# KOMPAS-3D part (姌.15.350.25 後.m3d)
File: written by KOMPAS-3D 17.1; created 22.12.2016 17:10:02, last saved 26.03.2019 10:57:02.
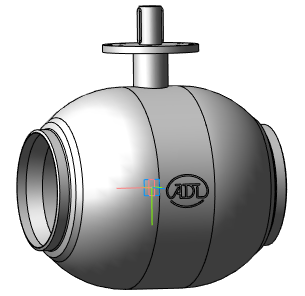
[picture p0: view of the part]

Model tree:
1. Операция без истории:3  (labels: Сталь 20  ГОСТ 1050-88)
